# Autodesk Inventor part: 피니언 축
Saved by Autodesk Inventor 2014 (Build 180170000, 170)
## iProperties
Created: 2024-11
Part Number: 피니언 축
Material: 일반
Document SubType Name: Modeling
Designer: dg
Density: 1 g/cm^3
Appearance: 기본값
Author: dg
Author: jhkim
Creation Date: 2024-10-25
Sending System: Autodesk Inventor 2025
Preprocessor: ST-DEVELOPER v20
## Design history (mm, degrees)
node "피니언 축1"
node "솔리드1"
node "기준1"
